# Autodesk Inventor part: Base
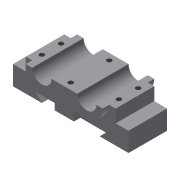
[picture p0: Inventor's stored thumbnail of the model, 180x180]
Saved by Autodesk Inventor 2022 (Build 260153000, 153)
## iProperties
Created: 2002-02
Part Number: Base
Document SubType Name: Modeling
Designer: ***
Density: 1 g/cm^3
Material: Generic
Appearance: Default
Control State: 0
Master: False
Checked Out: False
Shininess: 77.0
Length Units: 11269
Angle Units: 11279
Time Units: 11290
Mass Units: 11283
Length Display Precision: 3
Angle Display Precision: 2
Density: 0.0
Volumn: 0.0
Area: 0.0
PropertySet Name: Model Information
Author: ***
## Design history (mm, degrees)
sketch "Sketch2"
  geometry: L1 (-10.066, -1.263)-(24.934, -1.263); L2 (37.434, 11.237)-(32.434, 11.237); L3 (17.434, 11.237)-(-2.566, 11.237); L4 (-17.566, 11.237)-(-22.566, 11.237); A1 r 12.5 centre (-10.066, 11.237) between (-22.566, 11.237) and (-10.066, -1.263); A2 r 12.5 centre (24.934, 11.237) between (24.934, -1.263) and (37.434, 11.237); A3 r 7.5 centre (24.934, 11.237) between (17.434, 11.237) and (32.434, 11.237); A4 r 7.5 centre (-10.066, 11.237) between (-17.566, 11.237) and (-2.566, 11.237)
  constraints: 8 end point, 8 point on circle, 4 centre point, 3 horizontal, 3 parallel, 2 coincident, 2 equal radius, 2 tangent
  dimensions: "d0" = 12.5 radius of A1; "d1" = 7.5 radius of A4; "d2" = 35 distance of A1.centre A2.centre; "d3" = 12.5 distance between parallel lines of L3 L1
extrude "Extrusion1" new body sketch "Sketch2" stored distance "d4" = 40; taper "d5" = 0 deg
sketch "Sketch4"
  geometry: L1 (-27.566, 1.237)-(-37.566, 1.237); L2 (-37.566, 1.237)-(-37.566, -13.763); L3 (-37.566, -13.763)-(-15.066, -13.763); L4 (-15.066, -13.763)-(-20.066, -8.763); L5 (-20.066, -8.763)-(34.934, -8.763); L6 (34.934, -8.763)-(29.934, -13.763); L7 (29.934, -13.763)-(52.434, -13.763); L8 (52.434, -13.763)-(52.434, 1.237); L9 (52.434, 1.237)-(42.434, 1.237); L10 (24.934, -1.263)-(-10.066, -1.263); L11 (-17.566, 11.237)-(-22.566, 11.237) reference; L12 (37.434, 11.237)-(32.434, 11.237) reference; L13 (-22.566, 11.237)-(-27.566, 11.237); L14 (-27.566, 11.237)-(-27.566, 1.237); L15 (37.434, 11.237)-(42.434, 11.237); L16 (42.434, 11.237)-(42.434, 1.237); A1 r 12.5 centre (24.934, 11.237) between (24.934, -1.263) and (37.434, 11.237); A2 r 12.5 centre (-10.066, 11.237) between (-22.566, 11.237) and (-10.066, -1.263); A3 r 12.5 centre (24.934, 11.237) between (24.934, -1.263) and (37.434, 11.237) reference; A4 r 12.5 centre (-10.066, 11.237) between (-22.566, 11.237) and (-10.066, -1.263) reference
  constraints: 28 end point, 6 perpendicular, 5 equal length, 4 concentric, 4 parallel, 4 point on circle, 2 centre point, 2 collinear, 1 tangent
  dimensions: "d12" = 15 distance of L1.end L2.end; "d13" = 25 distance from line of L3 L11.end; "d14" = 90 distance between parallel lines of L2 L8; "d15" = 5 distance between parallel lines of L5 L7; "d16" = 22.5 distance of L2.end L3.end; "d24" = 5 distance of L12.start L15.end; "d25" = 15 distance from line of L8 L12.start
extrude "Extrusion3" join sketch "Sketch4" stored distance "d17" = 30; taper "d18" = 0 deg
sketch "Sketch5"
  geometry: L1 (-14.934, -1.263)-(0.066, -1.263); L2 (0.066, -1.263)-(0.066, -8.763); L3 (0.066, -8.763)-(-14.934, -8.763); L4 (-14.934, -8.763)-(-14.934, -1.263); L5 (10.066, -1.263)-(-24.934, -1.263) reference; 1 further point
  constraints: 8 end point, 2 parallel, 1 collinear, 1 horizontal, 1 perpendicular
  dimensions: "d19" = 7.5 distance of L1.end L2.end; "d20" = 15 distance of L2.end L3.end; "d21" = 15 distance from line of point (-29.934, -13.763) L4
extrude "Extrusion4" join sketch "Sketch5" distance "d22" = 40; taper "d23" = 0 deg
sketch "Sketch6"
  geometry: L1 (-5, -35)-(0, -35) reference; L2 (-5, -35)-(-5, -5) reference; 1 further point
  dimensions: "d26" = 7.5 distance from line of L1 point (0, -27.5); "d27" = 5 distance from line of L2 point (0, -27.5)
hole "Hole1" sketch "Sketch6" at (0, -27.5) diameter "d28" = 3.688; stored, may be unused: countersink angle "d32" = 82 deg, drill point angle "d34" = 0 deg; dims "d29" = 9, "d30" = 4, "d31" = 2, "d33" = 15
pattern_linear "Rectangular Pattern1" dims "d37" = 60, "d40" = 15
sketch "Sketch7"
  geometry: L1 (-20, -40)-(-20, -35) reference; L2 (0, -40)-(20, -40) reference; 1 further point
  dimensions: "d41" = 30 distance from line of L1 point (10, -35); "d42" = 5 distance from line of L2 point (10, -35)
hole "Hole2" sketch "Sketch7" at (10, -35) diameter "d43" = 3.688; stored, may be unused: countersink angle "d47" = 82 deg, drill point angle "d49" = 0 deg; dims "d44" = 9, "d45" = 4, "d46" = 2, "d48" = 15
pattern_linear "Rectangular Pattern2" dims "d52" = 30
body "Solid1"
